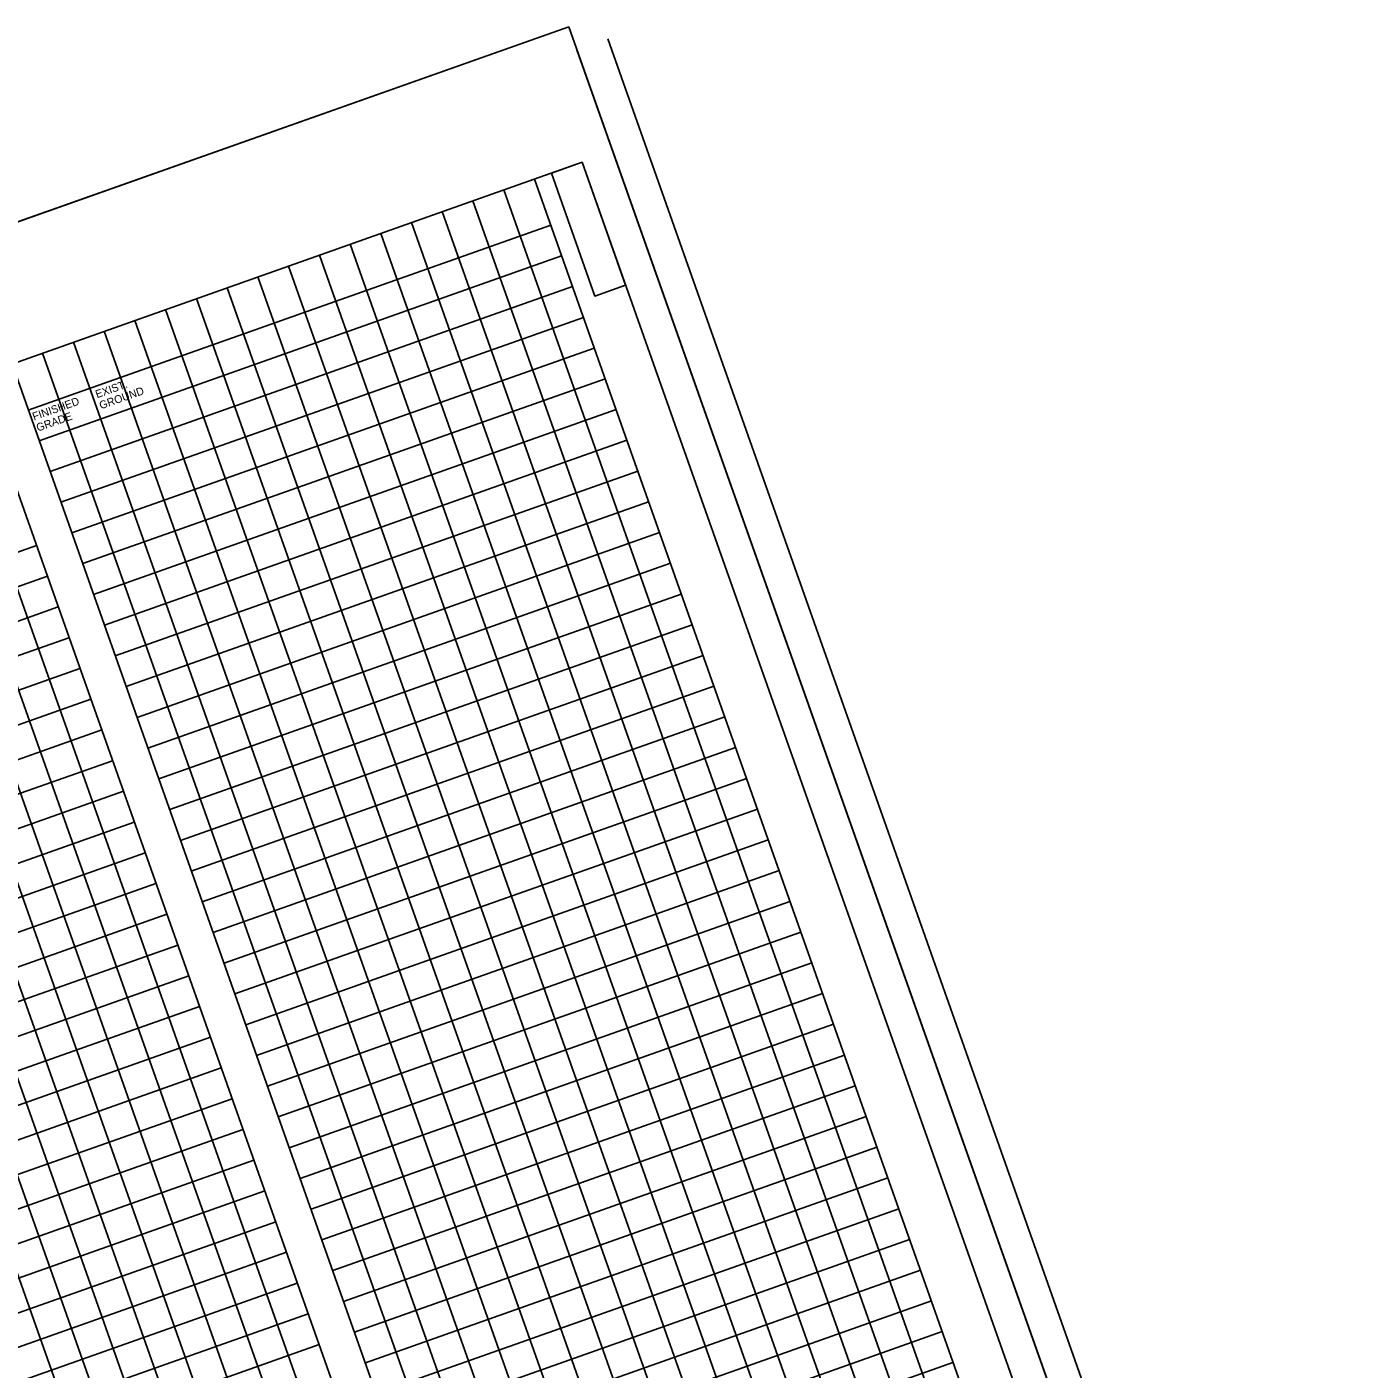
# Model space of a CAD drawing. Extents: x 2002686 to 2004357, y 1138437 to 1140501.
# Drawn here: x 2003325 to 2004357, y 1139472 to 1140501 of the extents above; entities that cross this region are included whole.
import ezdxf

# ---------------------------------------------------------------- set-up
doc = ezdxf.new("R2010")
doc.units = 0
for name, color, linetype in [('RD_SHT_Bndy', 7, 'Continuous'), ('RD_SHT_IplotShp', 7, 'Continuous'), ('RD_SHT_MjGrid', 7, 'Continuous'), ('RD_SHT_MnGrid', 7, 'Continuous'), ('RD_SHT_Snap', 7, 'Continuous'), ('RD_SHT_TX', 7, 'Continuous')]:
    doc.layers.add(name, color=color, linetype=linetype)

msp = doc.modelspace()

# ---------------------------------------------------------------- linework, layer by layer
at = {"layer": 'RD_SHT_Bndy'}
for p, q in [((2004357.1, 1138832.6), (2003770.2, 1140491.9)), ((2004333.6, 1138824.3), (2003746.6, 1140483.5)), ((2003750.6, 1140397.3), (2002760.7, 1140047.1)), ((2004309.2, 1138818.2), (2003750.6, 1140397.3))]:
    msp.add_line(p, q, dxfattribs=at)
msp.add_lwpolyline([(2003727, 1140388.9), (2003750.6, 1140397.3), (2003783.9, 1140303), (2003760.4, 1140294.7)], close=True, dxfattribs=at)
at = {"layer": 'RD_SHT_IplotShp'}
msp.add_lwpolyline([(2003740.4, 1140501.1), (2004340.7, 1138804.1), (2003303.7, 1138437.3), (2002703.4, 1140134.2)], close=True, dxfattribs=at)
at = {"layer": 'RD_SHT_MjGrid'}
for p, q in [((2003714, 1140384.4), (2004272.7, 1138805.3)), ((2003726.5, 1140349), (2003325.9, 1140207.3)), ((2003743.2, 1140301.9), (2003342.6, 1140160.2)), ((2003313.4, 1140242.6), (2003872, 1138663.5)), ((2003286.3, 1140233.1), (2003844.9, 1138654)), ((2003784.9, 1140184.1), (2003384.2, 1140042.3)), ((2003826.6, 1140066.2), (2003425.9, 1139924.5)), ((2003357.1, 1140032.7), (2002956.5, 1139891)), ((2003868.3, 1139948.4), (2003467.6, 1139806.6)), ((2003398.8, 1139914.9), (2002998.2, 1139773.1)), ((2003910, 1139830.5), (2003509.3, 1139688.8)), ((2003440.5, 1139797), (2003039.9, 1139655.3)), ((2003951.7, 1139712.7), (2003551, 1139570.9)), ((2003482.2, 1139679.2), (2003081.5, 1139537.5)), ((2003993.4, 1139594.8), (2003592.7, 1139453.1)), ((2003523.9, 1139561.4), (2003123.2, 1139419.6)), ((2004035, 1139477), (2003634.4, 1139335.3))]:
    msp.add_line(p, q, dxfattribs=at)
at = {"layer": 'RD_SHT_MnGrid'}
for p, q in [((2003666.9, 1140367.7), (2004225.5, 1138788.6)), ((2003690.5, 1140376.1), (2004186.6, 1138973.7)), ((2003643.3, 1140359.4), (2004202, 1138780.3)), ((2003619.8, 1140351), (2004178.4, 1138771.9)), ((2003596.2, 1140342.7), (2004154.8, 1138763.6)), ((2003572.6, 1140334.4), (2004131.3, 1138755.3)), ((2003734.9, 1140325.5), (2003334.2, 1140183.7)), ((2003525.5, 1140317.7), (2004084.1, 1138738.6)), ((2003549.1, 1140326), (2004107.7, 1138746.9)), ((2003501.9, 1140309.3), (2004060.6, 1138730.2)), ((2003478.4, 1140301), (2004037, 1138721.9)), ((2003454.8, 1140292.7), (2004013.4, 1138713.6)), ((2003751.6, 1140278.3), (2003350.9, 1140136.6)), ((2003407.6, 1140276), (2003966.3, 1138696.9)), ((2003431.2, 1140284.3), (2003989.8, 1138705.2)), ((2003384.1, 1140267.7), (2003942.7, 1138688.6)), ((2003759.9, 1140254.8), (2003359.2, 1140113)), ((2003360.5, 1140259.3), (2003919.1, 1138680.2)), ((2003336.9, 1140251), (2003895.6, 1138671.9)), ((2003262.7, 1140224.7), (2003758.8, 1138822.4)), ((2003768.2, 1140231.2), (2003367.6, 1140089.5)), ((2003239.1, 1140216.4), (2003797.8, 1138637.3)), ((2003215.6, 1140208), (2003774.2, 1138628.9)), ((2003776.6, 1140207.6), (2003375.9, 1140065.9)), ((2003192, 1140199.7), (2003750.6, 1138620.6)), ((2003144.9, 1140183), (2003703.5, 1138603.9)), ((2003168.4, 1140191.4), (2003727.1, 1138612.3)), ((2003121.3, 1140174.7), (2003679.9, 1138595.6)), ((2003097.7, 1140166.4), (2003656.4, 1138587.3)), ((2003793.2, 1140160.5), (2003392.6, 1140018.7)), ((2003801.6, 1140136.9), (2003400.9, 1139995.2)), ((2003809.9, 1140113.3), (2003409.3, 1139971.6)), ((2003332.1, 1140103.4), (2002931.5, 1139961.7)), ((2003818.3, 1140089.8), (2003417.6, 1139948)), ((2003340.5, 1140079.9), (2002939.8, 1139938.1)), ((2003348.8, 1140056.3), (2002948.1, 1139914.6)), ((2003834.9, 1140042.6), (2003434.3, 1139900.9)), ((2003843.3, 1140019.1), (2003442.6, 1139877.3)), ((2003365.5, 1140009.2), (2002964.8, 1139867.4)), ((2003373.8, 1139985.6), (2002973.1, 1139843.8)), ((2003851.6, 1139995.5), (2003450.9, 1139853.8)), ((2003860, 1139971.9), (2003459.3, 1139830.2)), ((2003382.2, 1139962), (2002981.5, 1139820.3)), ((2003390.5, 1139938.4), (2002989.8, 1139796.7)), ((2003876.6, 1139924.8), (2003476, 1139783.1)), ((2003885, 1139901.2), (2003484.3, 1139759.5)), ((2003407.2, 1139891.3), (2003006.5, 1139749.6)), ((2003893.3, 1139877.7), (2003492.6, 1139735.9)), ((2003415.5, 1139867.7), (2003014.8, 1139726)), ((2003901.6, 1139854.1), (2003501, 1139712.4)), ((2003423.8, 1139844.2), (2003023.2, 1139702.4)), ((2003432.2, 1139820.6), (2003031.5, 1139678.9)), ((2003918.3, 1139807), (2003517.6, 1139665.2)), ((2003926.7, 1139783.4), (2003526, 1139641.6)), ((2003448.9, 1139773.5), (2003048.2, 1139631.7)), ((2003935, 1139759.8), (2003534.3, 1139618.1)), ((2003457.2, 1139749.9), (2003056.5, 1139608.2)), ((2003943.3, 1139736.3), (2003542.7, 1139594.5)), ((2003465.5, 1139726.3), (2003064.9, 1139584.6)), ((2003473.9, 1139702.8), (2003073.2, 1139561)), ((2003960, 1139689.1), (2003559.3, 1139547.4)), ((2003968.3, 1139665.5), (2003567.7, 1139523.8)), ((2003490.5, 1139655.6), (2003089.9, 1139513.9)), ((2003976.7, 1139642), (2003576, 1139500.2)), ((2003498.9, 1139632.1), (2003098.2, 1139490.3)), ((2003985, 1139618.4), (2003584.4, 1139476.7)), ((2003507.2, 1139608.5), (2003106.6, 1139466.7)), ((2003515.6, 1139584.9), (2003114.9, 1139443.2)), ((2004001.7, 1139571.3), (2003601, 1139429.5)), ((2004010, 1139547.7), (2003609.4, 1139406)), ((2003532.2, 1139537.8), (2003131.6, 1139396)), ((2004018.4, 1139524.1), (2003617.7, 1139382.4)), ((2003540.6, 1139514.2), (2003139.9, 1139372.5)), ((2004026.7, 1139500.6), (2003626, 1139358.8)), ((2003548.9, 1139490.6), (2003148.2, 1139348.9))]:
    msp.add_line(p, q, dxfattribs=at)
at = {"layer": 'RD_SHT_Snap'}
msp.add_line((2002703.4, 1140134.2), (2003740.4, 1140501.1), dxfattribs=at)

# ---------------------------------------------------------------- texts
at = {"layer": 'RD_SHT_TX'}
for s, p in [('EXIST.', (2003378.6, 1140216.3)), ('GROUND', (2003381.6, 1140207.8)), ('FINISHED', (2003330.3, 1140199.2)), ('GRADE', (2003333.3, 1140190.7))]:
    msp.add_text(s, height=6, rotation=19.482, dxfattribs=at).set_placement(p)

doc.saveas('drawing.dxf')
